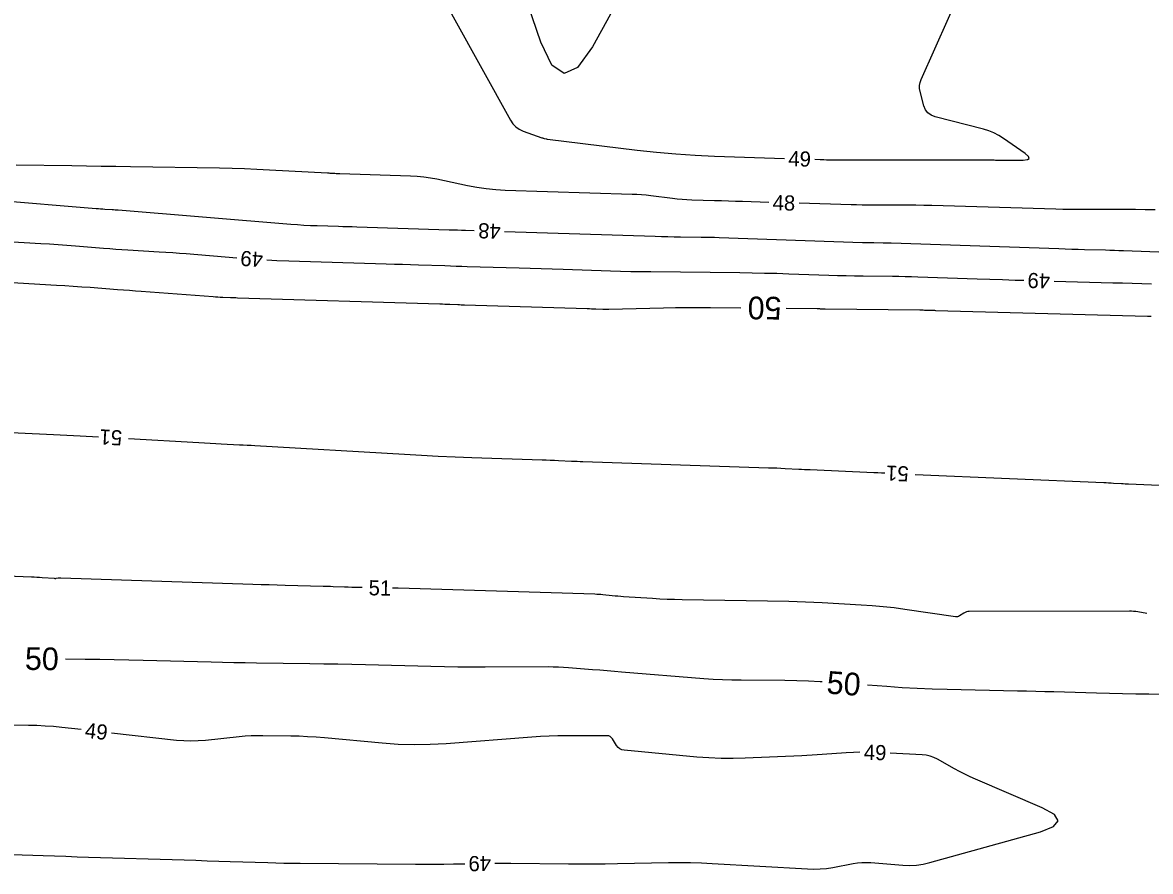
# Model space of a CAD drawing. Extents: x 2384780 to 2405861, y 547869 to 573706.
# Drawn here: x 2392751.8 to 2392900.7, y 552616.2 to 552728.4 of the extents above; entities that cross this region are included whole.
import ezdxf

# ---------------------------------------------------------------- set-up
doc = ezdxf.new("R2010")
doc.units = 0
doc.layers.add('Old_Level_60', color=7, linetype='Continuous')
doc.layers.add('Old_Level_61', color=7, linetype='Continuous')

msp = doc.modelspace()

# ---------------------------------------------------------------- linework, layer by layer
at = {"layer": 'Old_Level_60'}
for points in [[(2392874.96925, 552762.1605), (2392868.17375, 552760.808), (2392866.3365, 552760.3845), (2392864.535, 552759.85225), (2392862.76925, 552759.21125), (2392861.03925, 552758.4615), (2392846.272, 552751.52725), (2392843.29225, 552749.8445), (2392840.68175, 552747.76775), (2392838.44, 552745.297), (2392836.56775, 552742.4325), (2392827.04575, 552725.16025), (2392825.0895, 552722.42175), (2392823.30175, 552721.60825), (2392821.6825, 552722.71975), (2392820.23175, 552725.7565), (2392812.041, 552749.7265)], [(2392801.319, 552742.427), (2392816.21925, 552715.45325), (2392816.54075, 552714.97275), (2392816.93, 552714.57225), (2392817.3875, 552714.2515), (2392817.91275, 552714.0105), (2392820.379, 552713.124), (2392820.45125, 552713.0995), (2392820.52425, 552713.07725), (2392820.598, 552713.05775), (2392820.6725, 552713.0405), (2392820.99575, 552712.972), (2392821.0085, 552712.9695), (2392821.02125, 552712.96775), (2392821.03425, 552712.96625), (2392821.04725, 552712.96575), (2392821.08975, 552712.96425), (2392821.099, 552712.964), (2392821.108, 552712.96325), (2392821.117, 552712.9625), (2392821.126, 552712.9615), (2392832.96925, 552711.4985), (2392835.50925, 552711.214), (2392838.05375, 552710.9875), (2392840.60275, 552710.81875), (2392843.15625, 552710.708), (2392852.412, 552710.41175)], [(2392856.41, 552710.284), (2392857.14475, 552710.2605), (2392857.26, 552710.25675), (2392857.3755, 552710.25325), (2392857.49075, 552710.24975), (2392857.60625, 552710.24625), (2392857.98325, 552710.23525), (2392858.064, 552710.23325), (2392858.14475, 552710.23175), (2392858.2255, 552710.23075), (2392858.30625, 552710.23025), (2392879.913, 552710.19675), (2392879.967, 552710.1965), (2392880.02075, 552710.196), (2392880.07475, 552710.195), (2392880.12875, 552710.1935), (2392880.30475, 552710.1885), (2392880.3425, 552710.1875), (2392880.38025, 552710.18675), (2392880.418, 552710.1865), (2392880.45575, 552710.1865), (2392883.935, 552710.19225), (2392884.511, 552710.24675), (2392884.74775, 552710.40775), (2392884.64575, 552710.6755), (2392884.2045, 552711.04975), (2392881.352, 552713.04675), (2392880.72675, 552713.44425), (2392880.0735, 552713.78075), (2392879.39225, 552714.05625), (2392878.68325, 552714.27075), (2392872.308, 552715.89325), (2392871.7805, 552716.095), (2392871.3595, 552716.4045), (2392871.04525, 552716.822), (2392870.83775, 552717.3475), (2392870.33375, 552719.23975), (2392870.2605, 552719.6425), (2392870.25675, 552720.03975), (2392870.3225, 552720.4315), (2392870.45775, 552720.818), (2392877.672, 552737.09425)], [(2392850.36, 552704.5925), (2392846.84975, 552704.695), (2392845.931, 552704.72225), (2392845.01225, 552704.75), (2392844.0935, 552704.77825), (2392843.175, 552704.8075), (2392840.174, 552704.9035), (2392839.5315, 552704.93125), (2392838.89, 552704.97375), (2392838.24975, 552705.03075), (2392837.61075, 552705.1025), (2392834.7485, 552705.456), (2392834.13475, 552705.52475), (2392833.51975, 552705.5795), (2392832.9035, 552705.62), (2392832.2865, 552705.64675), (2392815.53225, 552706.18), (2392814.27425, 552706.248), (2392813.02275, 552706.37125), (2392811.77825, 552706.55025), (2392810.54025, 552706.78475), (2392806.5075, 552707.64125), (2392805.64075, 552707.8055), (2392804.7695, 552707.93075), (2392803.89375, 552708.017), (2392803.013, 552708.06475), (2392793.68, 552708.36175), (2392793.51825, 552708.36725), (2392793.3565, 552708.374), (2392793.195, 552708.3815), (2392793.0335, 552708.39), (2392792.50575, 552708.41925), (2392792.39275, 552708.4255), (2392792.27975, 552708.43175), (2392792.16675, 552708.438), (2392792.0535, 552708.44425), (2392784.38575, 552708.87), (2392782.74225, 552708.953), (2392781.09825, 552709.01975), (2392779.45375, 552709.07), (2392777.8085, 552709.104), (2392766.05225, 552709.28875), (2392764.114, 552709.31925), (2392762.1755, 552709.34975), (2392760.237, 552709.38025), (2392758.29875, 552709.41075), (2392750.9265, 552709.5265)], [(2392747.75975, 552704.91875), (2392761.508, 552703.786), (2392761.79525, 552703.76325), (2392762.08225, 552703.742), (2392762.3695, 552703.7225), (2392762.657, 552703.7045), (2392763.59575, 552703.6485), (2392763.797, 552703.636), (2392763.998, 552703.62225), (2392764.199, 552703.6075), (2392764.4, 552703.59175), (2392787.2315, 552701.72225), (2392788.092, 552701.65725), (2392788.95325, 552701.60325), (2392789.815, 552701.5605), (2392790.6775, 552701.52875), (2392793.49575, 552701.44275), (2392794.09975, 552701.42425), (2392794.7035, 552701.4055), (2392795.3075, 552701.38675), (2392795.9115, 552701.3675), (2392808.14375, 552700.97825), (2392808.678, 552700.96125), (2392809.21225, 552700.9445), (2392809.7465, 552700.928), (2392810.281, 552700.91175), (2392811.4345, 552700.8765)], [(2392901.35975, 552703.6125), (2392900.0575, 552703.62675), (2392898.7555, 552703.63625), (2392897.4535, 552703.64125), (2392896.15125, 552703.6415), (2392891.89775, 552703.6345), (2392890.98625, 552703.63625), (2392890.07475, 552703.64525), (2392889.1635, 552703.66125), (2392888.2525, 552703.68425), (2392871.86375, 552704.15975), (2392870.80525, 552704.187), (2392869.74675, 552704.20675), (2392868.688, 552704.21925), (2392867.62925, 552704.2245), (2392864.1705, 552704.22975), (2392863.42925, 552704.2335), (2392862.68825, 552704.2425), (2392861.94725, 552704.2565), (2392861.20625, 552704.2755), (2392854.35825, 552704.4755)], [(2392815.4325, 552700.751), (2392835.32975, 552700.11775), (2392836.16875, 552700.09325), (2392837.00775, 552700.07325), (2392837.847, 552700.05775), (2392838.68625, 552700.0465), (2392841.428, 552700.0175), (2392842.01525, 552700.0095), (2392842.60275, 552699.998), (2392843.19, 552699.983), (2392843.77725, 552699.96475), (2392862.70675, 552699.3145), (2392863.08425, 552699.30275), (2392863.462, 552699.293), (2392863.83975, 552699.2855), (2392864.2175, 552699.28), (2392865.4515, 552699.26575), (2392865.716, 552699.262), (2392865.9805, 552699.25675), (2392866.24475, 552699.25), (2392866.50925, 552699.2415), (2392888.661, 552698.48225), (2392889.50625, 552698.454), (2392890.35175, 552698.42725), (2392891.197, 552698.40175), (2392892.0425, 552698.37775), (2392894.80425, 552698.302), (2392895.396, 552698.28525), (2392895.98775, 552698.26675), (2392896.5795, 552698.247), (2392897.171, 552698.22575), (2392911.1455, 552697.70875)], [(2392740.913, 552699.97275), (2392754.212, 552699.17475), (2392755.35225, 552699.103), (2392756.49225, 552699.025), (2392757.63175, 552698.94075), (2392758.771, 552698.85), (2392762.49125, 552698.5435), (2392763.2885, 552698.48025), (2392764.08625, 552698.42125), (2392764.88425, 552698.36675), (2392765.6825, 552698.317), (2392769.83575, 552698.06925), (2392770.7255, 552698.01375), (2392771.615, 552697.95325), (2392772.504, 552697.888), (2392773.39275, 552697.81775), (2392780.067, 552697.27125)], [(2392784.057, 552696.993), (2392785.36475, 552696.928), (2392786.9295, 552696.87025), (2392799.82775, 552696.47725), (2392800.89025, 552696.4445), (2392801.95275, 552696.41175), (2392803.01525, 552696.3785), (2392804.078, 552696.34475), (2392807.54875, 552696.23425), (2392808.29275, 552696.21075), (2392809.0365, 552696.1875), (2392809.78025, 552696.1645), (2392810.524, 552696.14175), (2392817.35225, 552695.9335), (2392818.8155, 552695.88875), (2392820.27875, 552695.8435), (2392821.74175, 552695.7975), (2392823.205, 552695.75125), (2392829.4385, 552695.55275), (2392830.7745, 552695.514), (2392832.1105, 552695.482), (2392833.4465, 552695.45725), (2392834.783, 552695.4395), (2392846.5375, 552695.31475), (2392848.154, 552695.29275), (2392849.7705, 552695.26125), (2392851.3865, 552695.22025), (2392853.0025, 552695.1695), (2392858.28075, 552694.98825), (2392859.412, 552694.9525), (2392860.54325, 552694.9235), (2392861.67475, 552694.90075), (2392862.80625, 552694.8845), (2392866.68575, 552694.83975), (2392867.517, 552694.828), (2392868.348, 552694.81125), (2392869.179, 552694.78975), (2392870.01, 552694.76375), (2392877.8575, 552694.49475), (2392879.53925, 552694.4385), (2392881.221, 552694.38525), (2392882.90275, 552694.33475), (2392884.017, 552694.30325)], [(2392888.0155, 552694.193), (2392895.77575, 552693.98025), (2392897.053, 552693.9435), (2392898.33025, 552693.904), (2392899.6075, 552693.86125), (2392900.8845, 552693.8155)], [(2392734.32975, 552674.91825), (2392755.85575, 552673.9195), (2392756.73875, 552673.878), (2392757.6215, 552673.8355), (2392758.5045, 552673.792), (2392759.38725, 552673.74775), (2392761.80175, 552673.62475)], [(2392765.79575, 552673.40475), (2392775.0855, 552672.864), (2392775.8195, 552672.822), (2392776.55325, 552672.78125), (2392777.28725, 552672.74175), (2392778.0215, 552672.7035), (2392780.4195, 552672.58125), (2392780.9335, 552672.5545), (2392781.44725, 552672.527), (2392781.961, 552672.49825), (2392782.47475, 552672.46875), (2392802.24575, 552671.3095), (2392804.464, 552671.1865), (2392806.68275, 552671.07775), (2392808.90225, 552670.983), (2392811.12225, 552670.90275), (2392820.41675, 552670.59575), (2392820.9505, 552670.577), (2392821.484, 552670.55575), (2392822.0175, 552670.53225), (2392822.551, 552670.50625), (2392824.293, 552670.4175), (2392824.6665, 552670.39925), (2392825.04, 552670.38275), (2392825.4135, 552670.368), (2392825.787, 552670.35475), (2392850.29725, 552669.54125), (2392850.8465, 552669.522), (2392851.39575, 552669.50025), (2392851.945, 552669.476), (2392852.494, 552669.4495), (2392854.2875, 552669.3595), (2392854.67175, 552669.3405), (2392855.05625, 552669.322), (2392855.4405, 552669.30425), (2392855.825, 552669.28725), (2392864.2345, 552668.9205), (2392864.72975, 552668.8985), (2392865.225, 552668.87575), (2392865.6865, 552668.85375)], [(2392869.68175, 552668.66125), (2392894.57725, 552667.5785), (2392894.902, 552667.56375), (2392895.2265, 552667.54725), (2392895.551, 552667.5295), (2392895.8755, 552667.51025), (2392896.93525, 552667.44525), (2392897.16225, 552667.43175), (2392897.3895, 552667.41925), (2392897.61675, 552667.408), (2392897.844, 552667.3975), (2392924.10625, 552666.26125)], [(2392796.63, 552653.69725), (2392796.19875, 552653.704), (2392795.72975, 552653.71275), (2392795.26075, 552653.72425), (2392794.792, 552653.73875), (2392794.32325, 552653.75625), (2392792.792, 552653.8175), (2392792.464, 552653.83025), (2392792.13575, 552653.8415), (2392791.8075, 552653.8515), (2392791.47925, 552653.8605), (2392786.487, 552653.98675), (2392785.41725, 552654.01475), (2392784.3475, 552654.04525), (2392783.278, 552654.07775), (2392782.2085, 552654.1125), (2392756.82325, 552654.96325), (2392756.742, 552654.96375), (2392756.661, 552654.96), (2392756.5805, 552654.95175), (2392756.5, 552654.9395), (2392756.238, 552654.8915), (2392756.18175, 552654.88325), (2392756.12525, 552654.87825), (2392756.06875, 552654.877), (2392756.012, 552654.87925), (2392754.37725, 552654.99475), (2392754.02675, 552655.018), (2392753.67625, 552655.039), (2392753.32575, 552655.057), (2392752.975, 552655.0725), (2392728.06175, 552656.07675)], [(2392900.27325, 552650.28875), (2392899.0785, 552650.48375), (2392898.8015, 552650.52325), (2392898.5235, 552650.55125), (2392898.2445, 552650.568), (2392897.96475, 552650.5735), (2392876.8275, 552650.54825), (2392876.62875, 552650.534), (2392876.439, 552650.4915), (2392876.2575, 552650.42075), (2392876.08475, 552650.322), (2392875.53425, 552649.953), (2392875.4135, 552649.8865), (2392875.287, 552649.84475), (2392875.155, 552649.828), (2392875.0175, 552649.836), (2392868.325, 552650.81025), (2392866.8895, 552651.00325), (2392865.4505, 552651.1645), (2392864.0085, 552651.29425), (2392862.56325, 552651.39225), (2392857.39775, 552651.6855), (2392856.29075, 552651.743), (2392855.18325, 552651.78925), (2392854.07525, 552651.82475), (2392852.967, 552651.84925), (2392838.87975, 552652.08975), (2392837.902, 552652.11225), (2392836.9245, 552652.146), (2392835.94775, 552652.191), (2392834.97125, 552652.24775), (2392831.16875, 552652.49), (2392830.7925, 552652.516), (2392830.4165, 552652.5455), (2392830.041, 552652.579), (2392829.6655, 552652.61625), (2392828.44, 552652.74375), (2392828.17725, 552652.76875), (2392827.914, 552652.78875), (2392827.6505, 552652.804), (2392827.38675, 552652.8145), (2392801.4105, 552653.60225), (2392800.701, 552653.6225), (2392800.62925, 552653.62425)], [(2392759.53375, 552634.9295), (2392756.982, 552635.216), (2392755.884, 552635.32575), (2392754.78425, 552635.40875), (2392753.683, 552635.46525), (2392752.57975, 552635.495), (2392748.69675, 552635.553)], [(2392862.381, 552631.95125), (2392861.54725, 552631.92875), (2392860.57725, 552631.8735), (2392857.40925, 552631.64425), (2392856.73025, 552631.5975), (2392856.051, 552631.5555), (2392855.3715, 552631.51825), (2392854.69175, 552631.48575), (2392847.2305, 552631.15475), (2392845.63225, 552631.11125), (2392844.0355, 552631.12225), (2392842.43975, 552631.188), (2392840.8455, 552631.3085), (2392831.2335, 552632.19925), (2392830.92575, 552632.261), (2392830.657, 552632.38525), (2392830.4275, 552632.572), (2392830.237, 552632.82125), (2392829.6785, 552633.73825), (2392829.545, 552633.91), (2392829.38375, 552634.0325), (2392829.19525, 552634.106), (2392828.979, 552634.13), (2392823.6245, 552634.11725), (2392822.4775, 552634.10375), (2392821.33125, 552634.06925), (2392820.186, 552634.0135), (2392819.0415, 552633.9365), (2392807.74125, 552633.071), (2392805.6275, 552632.9535), (2392803.51475, 552632.9255), (2392801.4025, 552632.9865), (2392799.29075, 552633.13675), (2392791.67425, 552633.83975), (2392790.55575, 552633.932), (2392789.43625, 552634.0025), (2392788.31525, 552634.05125), (2392787.1935, 552634.078), (2392783.5265, 552634.13), (2392782.74125, 552634.1295), (2392781.957, 552634.105), (2392781.174, 552634.057), (2392780.392, 552633.98525), (2392775.93125, 552633.508), (2392774.9755, 552633.43175), (2392774.01975, 552633.40825), (2392773.06425, 552633.43675), (2392772.109, 552633.518), (2392763.509, 552634.48325)], [(2392814.17925, 552617.269), (2392814.52625, 552617.27175), (2392815.40275, 552617.273), (2392816.279, 552617.26875), (2392823.86775, 552617.20825), (2392825.49375, 552617.201), (2392827.11975, 552617.205), (2392828.74575, 552617.22025), (2392830.37175, 552617.24675), (2392837.1055, 552617.37975), (2392838.54825, 552617.394), (2392839.9905, 552617.38), (2392841.432, 552617.3375), (2392842.873, 552617.26675), (2392855.4635, 552616.52425), (2392856.29925, 552616.50025), (2392857.1315, 552616.52725), (2392857.96075, 552616.605), (2392858.78675, 552616.73375), (2392861.48, 552617.237), (2392862.058, 552617.3255), (2392862.63825, 552617.3755), (2392863.2205, 552617.38675), (2392863.80475, 552617.3595), (2392868.04275, 552617.02125), (2392868.94725, 552616.9885), (2392869.84375, 552617.035), (2392870.733, 552617.16075), (2392871.61425, 552617.366), (2392886.21275, 552621.437), (2392887.9485, 552622.1155), (2392888.56275, 552622.86925), (2392888.05525, 552623.69875), (2392886.42625, 552624.60375), (2392877.63725, 552628.388), (2392876.92675, 552628.7055), (2392876.2255, 552629.04175), (2392875.53375, 552629.39725), (2392874.8515, 552629.77175), (2392872.63825, 552631.02625), (2392872.155, 552631.26475), (2392871.6545, 552631.44275), (2392871.13625, 552631.56025), (2392870.6005, 552631.61725), (2392866.378, 552631.82425)], [(2392747.53325, 552618.51175), (2392754.5205, 552618.289), (2392756.01775, 552618.2415), (2392757.515, 552618.19425), (2392759.01225, 552618.1475), (2392760.5095, 552618.10125), (2392773.13725, 552617.71225), (2392774.656, 552617.66525), (2392776.175, 552617.618), (2392777.694, 552617.57), (2392779.21275, 552617.522), (2392784.1745, 552617.36375), (2392785.23775, 552617.333), (2392786.30125, 552617.3085), (2392787.36475, 552617.2905), (2392788.42825, 552617.27875), (2392803.67625, 552617.15725), (2392804.92825, 552617.15125), (2392806.18025, 552617.15325), (2392807.43225, 552617.16325), (2392808.684, 552617.181), (2392810.17975, 552617.207)]]:
    msp.add_lwpolyline(points, dxfattribs=at)
at = {"layer": 'Old_Level_61'}
for points in [[(2392746.76225, 552694.2425), (2392756.256, 552693.67275), (2392757.36975, 552693.60375), (2392758.483, 552693.5305), (2392759.596, 552693.453), (2392760.709, 552693.37125), (2392764.3435, 552693.09725), (2392765.12225, 552693.0385), (2392765.901, 552692.97975), (2392766.68, 552692.921), (2392767.45875, 552692.86225), (2392776.94725, 552692.14675), (2392777.26525, 552692.124), (2392777.58325, 552692.10425), (2392777.9015, 552692.087), (2392778.22, 552692.0725), (2392779.26025, 552692.0295), (2392779.48325, 552692.02075), (2392779.70625, 552692.0125), (2392779.92925, 552692.00475), (2392780.15225, 552691.99775), (2392806.904, 552691.1825), (2392807.227, 552691.17225), (2392807.55025, 552691.161), (2392807.87325, 552691.149), (2392808.19625, 552691.136), (2392809.25125, 552691.0925), (2392809.4775, 552691.0835), (2392809.7035, 552691.075), (2392809.92975, 552691.06725), (2392810.156, 552691.06), (2392826.356, 552690.56625), (2392826.64175, 552690.55725), (2392826.9275, 552690.54725), (2392827.213, 552690.53675), (2392827.49875, 552690.52525), (2392828.4315, 552690.4865), (2392828.6315, 552690.48), (2392828.8315, 552690.47675), (2392829.0315, 552690.47675), (2392829.2315, 552690.48), (2392836.45125, 552690.66225), (2392837.9985, 552690.6945), (2392839.54575, 552690.71275), (2392841.09325, 552690.717), (2392842.64075, 552690.7075), (2392846.65825, 552690.665)], [(2392852.658, 552690.60125), (2392856.73325, 552690.558), (2392856.836, 552690.55675), (2392856.93875, 552690.55475), (2392857.04175, 552690.552), (2392857.1445, 552690.54875), (2392857.48025, 552690.53725), (2392857.55225, 552690.535), (2392857.624, 552690.53325), (2392857.696, 552690.53175), (2392857.768, 552690.53075), (2392870.3035, 552690.3865), (2392870.50975, 552690.3835), (2392870.716, 552690.37925), (2392870.92225, 552690.374), (2392871.12825, 552690.3675), (2392871.8015, 552690.3445), (2392871.94575, 552690.33975), (2392872.09025, 552690.335), (2392872.2345, 552690.33075), (2392872.37875, 552690.32675), (2392900.37225, 552689.55875), (2392900.52275, 552689.5545), (2392900.67325, 552689.54975), (2392900.82375, 552689.54475)], [(2392857.38275, 552641.24225), (2392857.14075, 552641.2585), (2392855.58425, 552641.33525), (2392854.02675, 552641.3855), (2392852.46825, 552641.40925), (2392846.70575, 552641.44775), (2392845.4715, 552641.4675), (2392844.23825, 552641.51), (2392843.006, 552641.575), (2392841.7745, 552641.66325), (2392830.9095, 552642.54075), (2392829.94625, 552642.6185), (2392828.98275, 552642.69625), (2392828.01925, 552642.77425), (2392827.05575, 552642.852), (2392823.9085, 552643.10625), (2392823.23375, 552643.1535), (2392822.5585, 552643.18675), (2392821.88275, 552643.206), (2392821.2065, 552643.211), (2392812.86075, 552643.186), (2392811.0725, 552643.187), (2392809.28425, 552643.2005), (2392807.49625, 552643.2265), (2392805.70825, 552643.26525), (2392797.09675, 552643.4815), (2392795.25125, 552643.52525), (2392793.40575, 552643.56425), (2392791.56025, 552643.59775), (2392789.7145, 552643.6265), (2392782.69075, 552643.72575), (2392781.1855, 552643.74925), (2392779.6805, 552643.77675), (2392778.17575, 552643.80825), (2392776.67075, 552643.844), (2392767.7275, 552644.069), (2392765.811, 552644.1145), (2392763.8945, 552644.15475), (2392761.97775, 552644.18975), (2392760.061, 552644.21925), (2392757.4645, 552644.25575)], [(2392909.6885, 552639.4035), (2392900.5205, 552639.601), (2392898.79875, 552639.639), (2392897.07725, 552639.67875), (2392895.3555, 552639.7205), (2392893.634, 552639.764), (2392888.0105, 552639.9095), (2392886.80525, 552639.94), (2392885.60025, 552639.96925), (2392884.395, 552639.99725), (2392883.19, 552640.024), (2392873.90225, 552640.22575), (2392871.9125, 552640.28225), (2392869.92425, 552640.365), (2392867.93725, 552640.4745), (2392865.9515, 552640.61025), (2392863.36675, 552640.80425)]]:
    msp.add_lwpolyline(points, dxfattribs=at)

# ---------------------------------------------------------------- texts
at = {"layer": 'Old_Level_60'}
for s, rotation, p in [('49', 358.1672667, (2392852.8995, 552709.39575)), ('48', 358.3262611, (2392850.827, 552703.57825)), ('48', 178.2030361, (2392814.968, 552701.767)), ('49', 176.010975, (2392783.60725, 552698.0115)), ('49', 178.4216944, (2392887.5235, 552695.20675)), ('51', 176.8470194, (2392764.98625, 552674.45575)), ('51', 177.2434056, (2392868.8645, 552669.69825)), ('51', 358.9534611, (2392797.47775, 552652.68725)), ('49', 353.5953556, (2392759.93875, 552633.87775)), ('49', 358.1816361, (2392862.86925, 552630.9685)), ('49', 180.8860028, (2392813.644, 552618.26475))]:
    msp.add_text(s, height=2, rotation=rotation, dxfattribs=at).set_placement(p)
at = {"layer": 'Old_Level_61'}
for rotation, p in [(179.3921222, (2392852.03575, 552692.108)), (359.1959806, (2392752.082, 552642.831)), (355.8135944, (2392857.91, 552639.70525))]:
    msp.add_text('50', height=3, rotation=rotation, dxfattribs=at).set_placement(p)

doc.saveas('drawing.dxf')
